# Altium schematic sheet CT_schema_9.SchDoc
size 391 x 238 mm
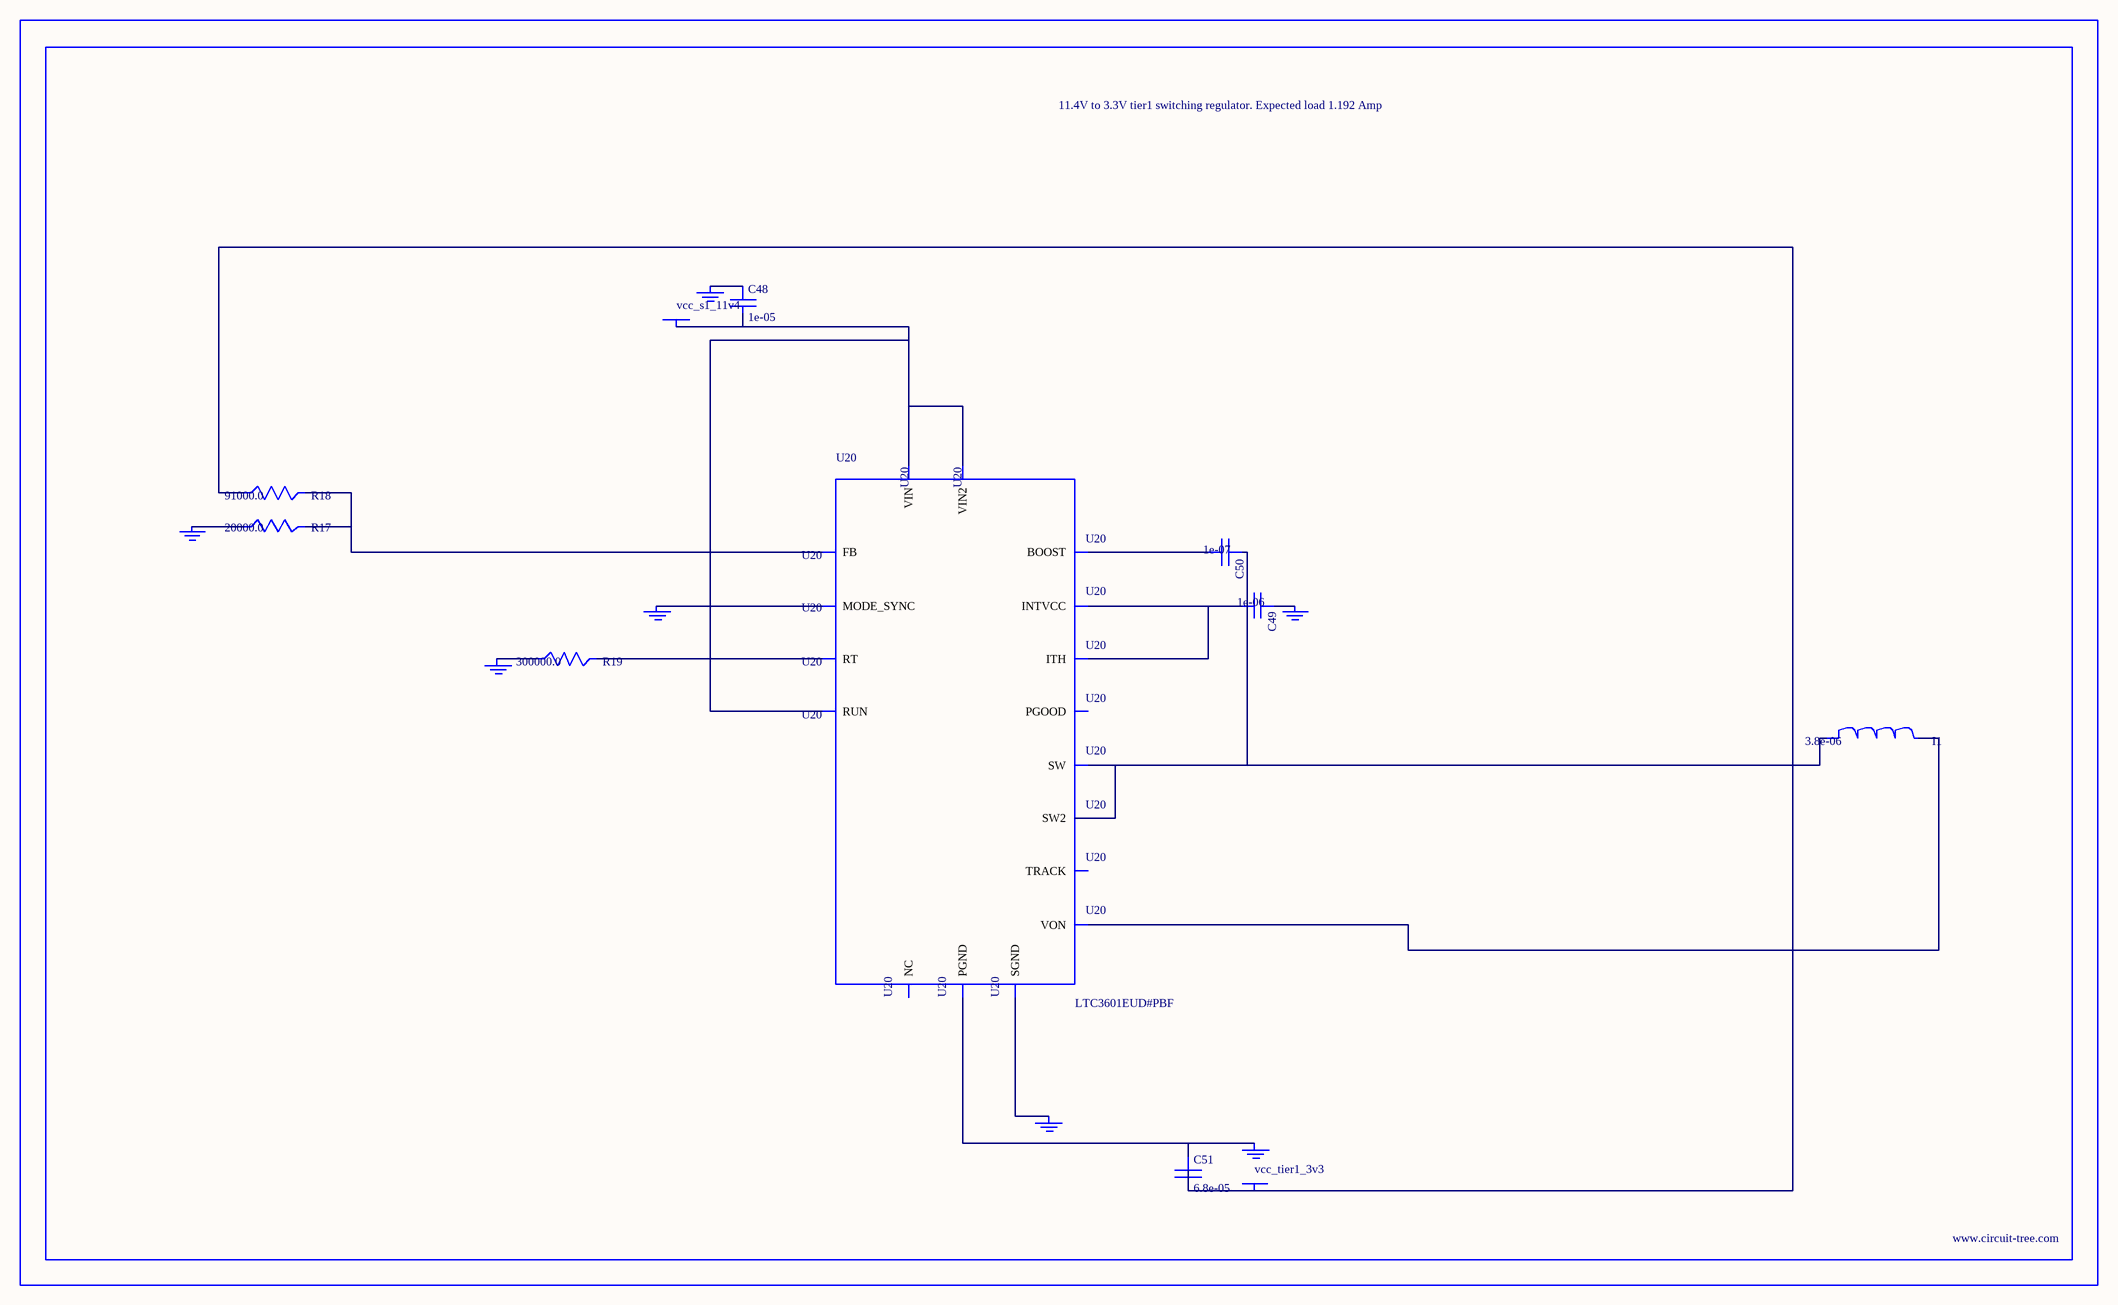
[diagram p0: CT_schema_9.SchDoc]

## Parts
BORDER8  (no value)
C48  1e-05  [C0805]
C49  1e-06  [C0603]
C50  1e-07  [C0402]
C51  6.8e-05  [2220]
GND_INSTANCE_8_0  (no value)
GND_INSTANCE_8_1  (no value)
GND_INSTANCE_8_2  (no value)
GND_INSTANCE_8_3  (no value)
GND_INSTANCE_8_4  (no value)
GND_INSTANCE_8_5  (no value)
GND_INSTANCE_8_6  (no value)
I1  3.8e-06  [DR1040]
POWER_INSTANCE_8_0  vcc_s1_11v4
POWER_INSTANCE_8_1  vcc_tier1_3v3
R17  20000.0  [R0603]
R18  91000.0  [R0603]
R19  300000.0  [R0603]
U20  LTC3601EUD#PBF  [QFN-16_EP]

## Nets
NetC48_1: C48.1 GND_INSTANCE_8_5.0(GND)
NetC48_2: C48.2 POWER_INSTANCE_8_0.0(PWR) U20.14(RUN) U20.15(VIN) U20.16(VIN2)
NetC49_1: C49.1 GND_INSTANCE_8_1.0(GND)
NetC49_2: C49.2 U20.7(INTVCC) U20.12(ITH)
NetC50_1: C50.1 I1.1 U20.3(SW) U20.4(SW2)
NetC50_2: C50.2 U20.6(BOOST)
NetC51_1: C51.1 GND_INSTANCE_8_6.0(GND) U20.17(PGND)
NetC51_2: C51.2 I1.2 POWER_INSTANCE_8_1.0(PWR) R18.1 U20.8(VON)
NetGND_INSTANCE_8_0_0: GND_INSTANCE_8_0.0(GND) U20.1(MODE_SYNC)
NetGND_INSTANCE_8_2_0: GND_INSTANCE_8_2.0(GND) U20.9(SGND)
NetGND_INSTANCE_8_3_0: GND_INSTANCE_8_3.0(GND) R19.1
NetGND_INSTANCE_8_4_0: GND_INSTANCE_8_4.0(GND) R17.1
NetR17_2: R17.2 R18.2 U20.11(FB)
NetR19_2: R19.2 U20.10(RT)

Not connected (* = marked no-connect by the designer): U20 2(PGOOD) 5(NC) 13(TRACK)

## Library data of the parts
BORDER8 = BORDER_PAGE8
C48 = C0805C106K8RACTU
C49 = C0603C105K3RACTU
C50 = C0402C104K3RACTU
C51 = C5750X5R1A686M
GND_INSTANCE_8_0-GND_INSTANCE_8_6 = GND
I1 = DR1040-3R8-R
POWER_INSTANCE_8_0 POWER_INSTANCE_8_1 = PWR
R17 = RC0603JR-0720KL
R18 = RC0603JR-0791KL
R19 = RC0603JR-07300KL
